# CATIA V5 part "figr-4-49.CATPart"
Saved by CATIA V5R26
Part number: Part1
Bounding box of the stored display mesh (mm): x -89.975 to 89.975, y -89.975 to 89.975, z 0 to 190
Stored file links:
  D:\_Deepak\CATIA\CATIA V5-6R2016_Deepak\Resources\Part files\Partfiles\c04_catia_v5_6r2016_prt\figr-4-49.CATPart
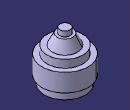
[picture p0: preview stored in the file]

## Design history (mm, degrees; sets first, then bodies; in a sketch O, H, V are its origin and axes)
Set1
  Line1 "Y Axis": stored without definition
  Line2 "Y Axis": stored without definition
  Line3 "X Axis": stored without definition
  Line4 "Z Axis": stored without definition
Body1 (main body)
  Sketch1 on yz-plane, origin (0, 0, 0), H (0, 1, 0), V (0, 0, 1)
    line L1 (0, 0) -> (80, 0)
    line L2 (80, 0) -> (80, 30)
    line L3 (80, 30) -> (90, 30)
    line L4 (90, 30) -> (90, 100)
    line L5 (90, 100) -> (70, 100)
    line L6 (70, 100) -> (70, 130)
    line L7 (70, 130) -> (50, 130)
    line L8 (50, 130) -> (30, 170)
    line L9 (30, 170) -> (20, 170)
    line L10 (20, 170) -> (20, 190)
    line L11 (20, 190) -> (0, 190)
    point P11 (0, 190)
    line L12 (0, 190) -> (0, 0)
    axis line L13 (0, -40) -> (0, 230)
    point P12 (0, -40)
    point P13 (0, 230)
    horizontal: L1 H, L3 H, L5 H, L7 H, L9 H, L11 H
    vertical: L2 V, L4 V, L6 V, L10 V, L12 V, L13 V
    coincidence: P11 V, P12 V, P13 L8
  Shaft1: profile Sketch1, axis Sketch1.L13, angle 360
